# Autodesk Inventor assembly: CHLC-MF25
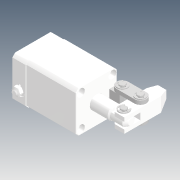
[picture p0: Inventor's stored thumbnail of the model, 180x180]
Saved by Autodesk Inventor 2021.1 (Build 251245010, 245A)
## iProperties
Company: Microsoft
Created: 2019-11
Part Number: CHLC-MF25
Description: STEP AP214
Document SubType Name: Assembly
Designer: user
Title: CHLC-MF25.STEP
Author: Windows
Revision Number: ÈÎºÎ
Sending System: SolidWorks 2015
Preprocessor: SwSTEP 2.0
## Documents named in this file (13)
- D:\Vault_2016\Projekty\Clamptek\Hydraulic\CHLC\CHLC-25\Inventor\CHLC-MF25\CHLC-MF25.iam
- D:\Vault_2016\Projekty\Clamptek\Hydraulic\CHLC\CHLC-25\Inventor\CHLC-MF25\chlc-mf25hg.ipt
- D:\Vault_2016\Projekty\Clamptek\Hydraulic\CHLC\CHLC-25\Inventor\CHLC-MF25\chlc-mf25bt.ipt
- D:\Vault_2016\Projekty\Clamptek\Hydraulic\CHLC\CHLC-25\Inventor\CHLC-MF25\CHLC-25HSG.ipt
- D:\Vault_2016\Projekty\Clamptek\Hydraulic\CHLC\CHLC-25\Inventor\CHLC-MF25\CHLC-25CX.ipt
- D:\Vault_2016\Projekty\Clamptek\Hydraulic\CHLC\CHLC-25\Inventor\CHLC-MF25\CHLC-25DX.ipt
- D:\Vault_2016\Projekty\Clamptek\Hydraulic\CHLC\CHLC-25\Inventor\CHLC-MF25\CHLC-25KKDC.ipt
- D:\Vault_2016\Projekty\Clamptek\Hydraulic\CHLC\CHLC-25\Inventor\CHLC-MF25\CHLC-25LG.ipt
- D:\Vault_2016\Projekty\Clamptek\Hydraulic\CHLC\CHLC-25\Inventor\CHLC-MF25\M6.ipt
- D:\Vault_2016\Projekty\Clamptek\Hydraulic\CHLC\CHLC-25\Inventor\CHLC-MF25\TXF_ASM.iam
- D:\Vault_2016\Projekty\Clamptek\Hydraulic\CHLC\CHLC-25\Inventor\CHLC-MF25\M6LC.ipt
- D:\Vault_2016\Projekty\Clamptek\Hydraulic\CHLC\CHLC-25\Inventor\CHLC-MF25\CHLC-25ZC.ipt
- D:\Vault_2016\Projekty\Clamptek\Hydraulic\CHLC\CHLC-25\Inventor\CHLC-MF25\Ñ¹±Û.ipt
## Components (20 placed, 20 different names)
1. chlc-mf25hg_1
2. chlc-mf25bt_2
3. CHLC-25HSG_3
4. CHLC-25CX_4
5. CHLC-25DX_5
6. CHLC-25KKDC_6
7. CHLC-25LG_7
8. M6_8
9. TXF_ASM_9 [sub-assembly]
10. CHLC-25CX_10
11. CHLC-25LG_11
12. CHLC-25KKDC_12
13. CHLC-25KKDC_13
14. CHLC-25KKDC_14
15. CHLC-25KKDC_15
16. CHLC-25KKDC_16
17. M6LC_17
18. M6LC_18
19. CHLC-25ZC_19
20. Ñ¹±Û_20
